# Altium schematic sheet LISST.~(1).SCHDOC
size B
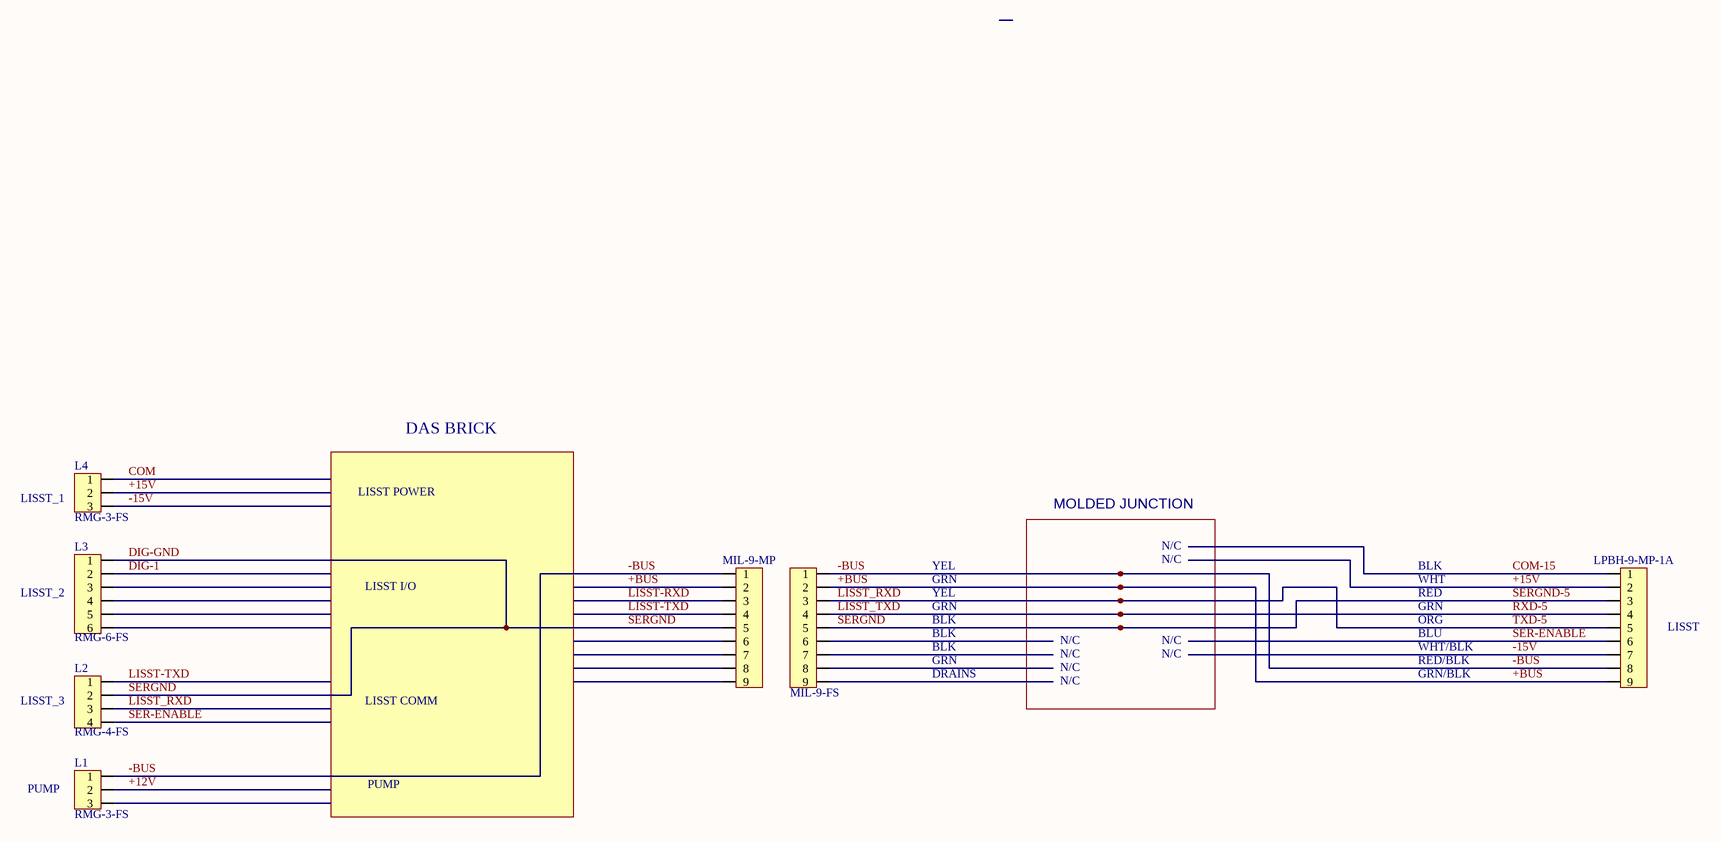
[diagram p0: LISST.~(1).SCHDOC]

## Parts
L1  RMG-3-FS  [SIP6]
L2  RMG-4-FS  [SIP6]
L3  RMG-6-FS  [SIP6]
L4  RMG-3-FS  [SIP6]
LPBH-9-MP-1A  IMPULSE  [SIP7]  (value not drawn)
MIL-9-FS  IMPULSE  [SIP7]  (value not drawn)
MIL-9-MP  IMPULSE  [SIP7]  (value not drawn)

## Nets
+12V: L1.2
+15V: L4.2 LPBH-9-MP-1A.2
+BUS: LPBH-9-MP-1A.9 MIL-9-FS.2 MIL-9-MP.2
-15V: L4.3 LPBH-9-MP-1A.7
-BUS: L1.1 LPBH-9-MP-1A.8 MIL-9-FS.1 MIL-9-MP.1
COM: L4.1
COM-15: LPBH-9-MP-1A.1
DIG-1: L3.2
DIG-GND: L2.2 L3.1 LPBH-9-MP-1A.3 MIL-9-FS.5 MIL-9-MP.5  [also labelled SERGND, SERGND-5]
LISST-RXD: MIL-9-MP.3
LISST-TXD: L2.1 MIL-9-MP.4
LISST_RXD: L2.3 LPBH-9-MP-1A.5 MIL-9-FS.3  [also labelled TXD-5]
LISST_TXD: LPBH-9-MP-1A.4 MIL-9-FS.4  [also labelled RXD-5]
SER-ENABLE: L2.4 LPBH-9-MP-1A.6

Not connected (* = marked no-connect by the designer): L1 3; L3 3 4 5 6; MIL-9-FS 6 7 8 9; MIL-9-MP 6 7 8 9

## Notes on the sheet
- DAS BRICK
- (near L4) LISST_1
- LISST POWER
- MOLDED JUNCTION
- YEL
- GRN
- N/C
- BLK
- WHT
- (near L3) LISST_2
- LISST I/O
- RED
- ORG
- BLU
- WHT/BLK
- (near LPBH-9-MP-1A) LISST
- (near L2) LISST_3
- LISST COMM
- DRAINS
- RED/BLK
- GRN/BLK
- PUMP

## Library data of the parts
L1 L4 = CON3: Connector
L2 = CON4: Connector
L3 = CON6: Connector
LPBH-9-MP-1A MIL-9-FS MIL-9-MP = CON9: Connector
